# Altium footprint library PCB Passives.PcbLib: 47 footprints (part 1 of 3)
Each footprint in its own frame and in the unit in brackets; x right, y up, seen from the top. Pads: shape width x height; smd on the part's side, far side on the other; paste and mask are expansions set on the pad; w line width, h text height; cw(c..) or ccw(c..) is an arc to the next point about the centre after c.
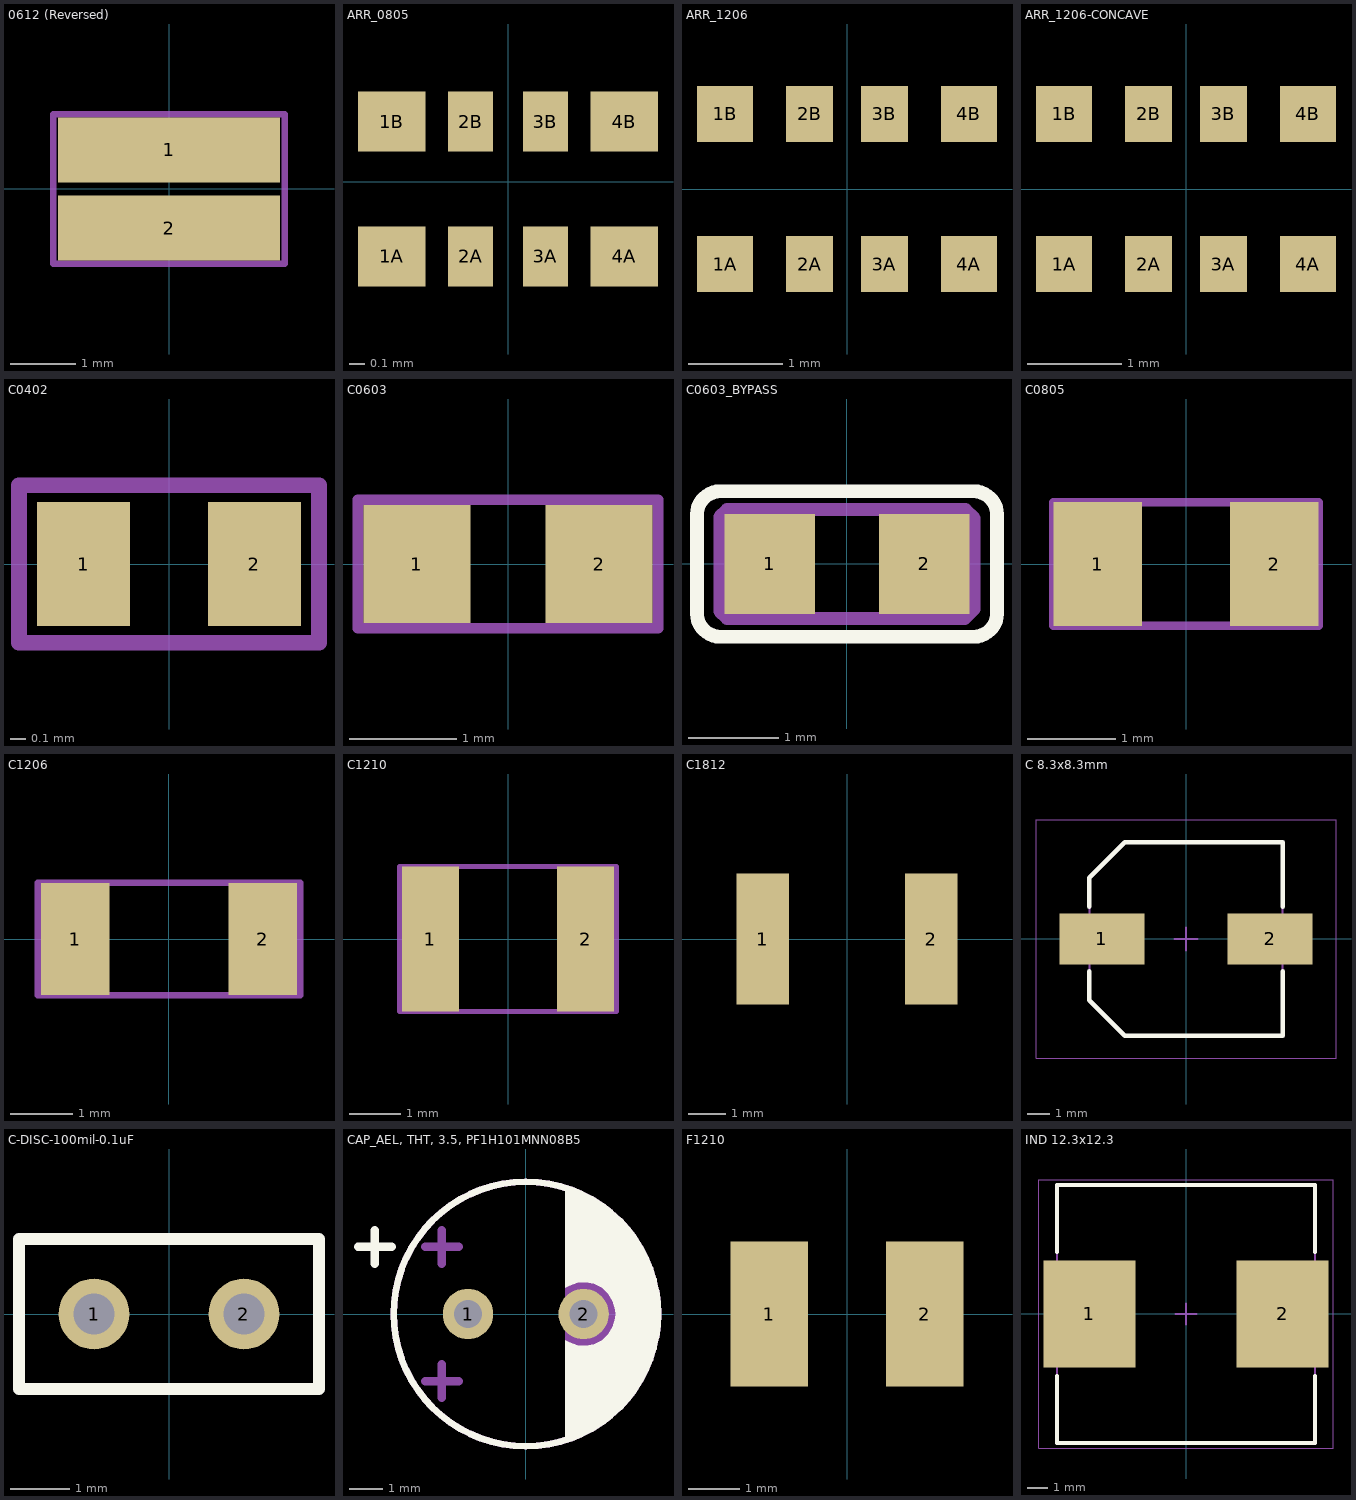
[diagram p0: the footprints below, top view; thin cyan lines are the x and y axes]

## 0612 (Reversed) [mm] "Chip Resistor, 2-Leads, Body 1,60x3,20mm, IPC Medium Density"
height 0.6
pads (2):
  rect 3.4x1 smd: 1(0,0.6) 2(0,-0.6)
Mechanical 29:
  lines w0.1: -1.778,-1.143 -1.778,1.143 1.778,1.143 1.778,-1.143 -1.778,-1.143
  text ".Designator" at -1.165,-0.3 h0.7
3D body "RESC1632X06N.step": height 0.6, standoff 0, extent -1.7,-0.9 1.7,0.9

## ARR_0805 [mm]
pads (8):
  rect 0.45x0.4 smd: 1A(-0.775,-0.5) 1B(-0.775,0.4) 4A(0.775,-0.5) 4B(0.775,0.4)
  rect 0.3x0.4 smd: 2A(-0.25,-0.5) 2B(-0.25,0.4) 3A(0.25,-0.5) 3B(0.25,0.4)
3D body "User Library-YC124.step": height 0.36, standoff 0, extent -1,-0.55 1,0.45

## ARR_1206 [mm]
height 0.6
pads (8):
  rect 0.6x0.6 smd: 1A(-1.3,-0.8) 1B(-1.3,0.8) 4A(1.3,-0.8) 4B(1.3,0.8)
  rect 0.5x0.6 smd: 2A(-0.4,-0.8) 2B(-0.4,0.8) 3A(0.4,-0.8) 3B(0.4,0.8)
3D body "User Library-YC164.step": height 0.55, standoff 0, extent -1.6,-0.8 1.6,0.8

## ARR_1206-CONCAVE [mm]
height 0.6
pads (8):
  rect 0.6x0.6 smd: 1A(-1.3,-0.8) 1B(-1.3,0.8) 4A(1.3,-0.8) 4B(1.3,0.8)
  rect 0.5x0.6 smd: 2A(-0.4,-0.8) 2B(-0.4,0.8) 3A(0.4,-0.8) 3B(0.4,0.8)
3D body "CAT16-x4.stp": height 0.6, standoff 0, extent -1.775,-0.825 1.575,0.925

## C0402 [mm] "0402 ceramic capacitor"
pads (2):
  rect 0.6x0.8 smd: 1(-0.55,0) 2(0.55,0)
Mechanical 29:
  lines w0.1: -0.965,-0.508 -0.965,0.508 0.965,0.508 0.965,-0.508 -0.965,-0.508
  text ".Designator" at -0.787,-0.279 h0.6
3D body "CAP_0402.step": height 0.5, standoff 0, extent -0.5,-0.25 0.5,0.25

## C0603 [mm] "0603 ceramic capacitor"
pads (2):
  rect 1x1.1 smd: 1(-0.85,0) 2(0.85,0)
Mechanical 29:
  lines w0.1: -1.4,-0.6 -1.4,0.6 1.4,0.6 1.4,-0.6 -1.4,-0.6
  text ".Designator" at -1.2,-0.2 h0.6
3D body "CAP_0603.step": height 0.8, standoff 0, extent -0.8,-0.4 0.8,0.4

## C0603_BYPASS [mm] "0603 ceramic capacitor"
pads (2):
  rect 1x1.1 smd: 1(-0.85,0) 2(0.85,0)
Top Overlay:
  lines w0.152: -1.651,-0.546 ccw(c-1.397,-0.546) -1.397,-0.8 1.397,-0.8 ccw(c1.397,-0.546) 1.651,-0.546 1.651,0.546 ccw(c1.397,0.546) 1.397,0.8 -1.397,0.8 ccw(c-1.397,0.546) -1.651,0.546 -1.651,-0.546
Mechanical 29:
  lines w0.14: -1.4,-0.521 -1.4,0.521 -1.321,0.6 1.305,0.6 1.4,0.505 1.4,-0.495 1.295,-0.6 -1.321,-0.6 -1.4,-0.521
  text ".Designator" at -0.635,-0.254 h0.51
3D body "CAP_0603.step": height 0.8, standoff 0, extent -0.8,-0.4 0.8,0.4

## C0805 [mm] "0805 ceramic capacitor"
pads (2):
  rect 1x1.4 smd: 1(-1,0) 2(1,0)
Mechanical 29:
  lines w0.1: -1.5,-0.7 1.5,-0.7 1.5,0.7 -1.5,0.7 -1.5,-0.7
  text ".Designator" at -1.3,-0.2 h0.6
3D body "CAP_0805.step": height 0.6, standoff 0, extent -1,-0.625 1,0.625

## C1206 [mm] "1206 ceramic capacitor"
pads (2):
  rect 1.1x1.8 smd: 1(-1.5,0) 2(1.5,0)
Mechanical 29:
  lines w0.1: -2.1,-0.9 -2.1,0.9 2.1,0.9 2.1,-0.9 -2.1,-0.9
  text ".Designator" at -1.8,-0.233 h0.7
3D body "CAP_1206.step": height 0.76, standoff -0.01, extent -1.6,-0.8 1.6,0.8

## C1210 [mm] "1210 capacitor"
pads (2):
  rect 1.1x2.8 smd: 1(-1.5,0) 2(1.5,0)
Mechanical 29:
  lines w0.1: -2.1,-1.4 2.1,-1.4 2.1,1.4 -2.1,1.4 -2.1,-1.4
  text ".Designator" at -1.8,-0.4 h0.8
3D body "User Library-SMD CAPACITOR.step": height 0.77, standoff -0.01, extent -1.6,-1.25 1.6,1.25

## C1812 [mm] "1812 capacitor"
pads (2):
  rect 1.4x3.5 smd: 1(-2.25,0) 2(2.25,0)
3D body "User Library-SMD CAPACITOR(1).step": height 1, standoff 0, extent -2.25,-1.6 2.25,1.6

## C 8.3x8.3mm [mm] "Aluminum Electrolytic Capacitor, Body 8.30x8.30x11.70mm, IPC Low Density"
height 11.7
pads (2):
  rect 3.75x2.25 smd: 1(-3.7,0) 2(3.7,0)
Top Overlay:
  lines w0.2: -4.25,-1.425 -4.25,-2.688 -2.688,-4.25 4.25,-4.25 4.25,-1.425 ; -4.25,1.425 -4.25,2.687 -2.688,4.25 4.25,4.25 4.25,1.425
Mechanical 13:
  lines w0.1: -4.25,-2.688 -2.688,-4.25 4.25,-4.25 4.25,4.25 -2.688,4.25 -4.25,2.687 -4.25,-2.688
Mechanical 15:
  lines w0.05: -6.6,-5.25 -6.6,5.25 6.6,5.25 6.6,-5.25 -6.6,-5.25
  lines w0.1: -0.5,0 0.5,0 ; 0,-0.5 0,0.5
3D body: height 3.9, standoff 0, extent -4.25,-4.25 4.25,4.25
3D body: height 11.7, standoff 0, extent -4.25,-4.25 4.25,4.247

## C-DISC-100mil-0.1uF [mm]
pads (2):
  round 1.2 hole 0.7: 1(-1.27,0) 2(1.27,0)
Top Overlay:
  lines w0.2: -2.54,-1.27 2.54,-1.27 2.54,1.27 -2.54,1.27 -2.54,-1.27
3D body "10pF Ceramic Disc 2.STEP": height 6.16, standoff -7.87, extent -2.35,-1.25 2.35,1.25

## CAP_AEL, THT, 3.5, PF1H101MNN08B5 [mm] "Capacitor: electrolytic; THT; 100uF; 50VDC; ¨8x11.5mm; Pitch:3.5mm"
pads (2):
  round 1.524 hole 0.85 paste-3: 1(-1.75,0) 2(1.75,0)
Top Overlay:
  circle w0.2: c0,0 r4
  region: 1.75,0
  region: 2.718,0 4,0 4,-0.318 3.9,-0.945 3.702,-1.548 3.411,-2.113 3.035,-2.625 2.583,-3.071 2.066,-3.44 1.497,-3.723 1.194,-3.818 1.194,-0.792 1.307,-0.86 1.555,-0.948 1.818,-0.965 2.075,-0.911 2.309,-0.79 2.501,-0.61 2.638,-0.385 2.709,-0.132
  region: 2.718,0 4,0 4,0.318 3.9,0.945 3.702,1.548 3.411,2.113 3.035,2.625 2.583,3.071 2.066,3.44 1.497,3.723 1.194,3.818 1.194,0.792 1.307,0.86 1.555,0.948 1.818,0.965 2.075,0.911 2.309,0.79 2.501,0.61 2.638,0.385 2.709,0.132
  lines w0.254: -5.08,2.032 -4.064,2.032 ; -4.572,1.524 -4.572,2.54
Mechanical 29:
  circle w0.2: c0,0 r4
  region: 1.194,3.817 1.497,3.723 2.066,3.44 2.583,3.071 3.035,2.625 3.411,2.113 3.702,1.548 3.9,0.945 4,0.317 4,-0.318 3.9,-0.945 3.702,-1.548 3.411,-2.113 3.035,-2.625 2.583,-3.071 2.066,-3.44 1.497,-3.723 1.194,-3.818
  region: 1.75,0
  lines w0.254: -3.048,-2.032 -2.032,-2.032 ; -3.048,2.032 -2.032,2.032 ; -2.54,-2.54 -2.54,-1.524 ; -2.54,1.524 -2.54,2.54
3D body "User Library-Cap electro 8x11_5x3_5mm.step": height 11.93, standoff -3.58, extent -4.025,-4.025 4.026,4.026

## F1210 [mm]
pads (2):
  rect 1.5x2.8 smd: 1(-1.5,0) 2(1.5,0)
3D body "User Library-Fuse1210.step": height 0.67, standoff 0, extent -1.607,-1.287 1.608,1.288

## IND 12.3x12.3 [mm] "Precision Wire Wound Inductor, 2-Leads, Body 12.30x12.30mm, IPC Medium Density"
height 6
pads (2):
  rect 4.4x5.1 smd: 1(-4.6,0) 2(4.6,0)
Top Overlay:
  lines w0.2: -6.15,-2.95 -6.15,-6.15 6.15,-6.15 6.15,-2.95 ; -6.15,2.95 -6.15,6.15 6.15,6.15 6.15,2.95
Mechanical 13:
  lines w0.1: -6.15,-6.15 6.15,-6.15 6.15,6.15 -6.15,6.15 -6.15,-6.15
Mechanical 15:
  lines w0.05: -7.025,-6.4 7.025,-6.4 7.025,6.4 -7.025,6.4 -7.025,-6.4
  lines w0.1: -0.5,0 0.5,0 ; 0,-0.5 0,0.5
3D body: height 6, standoff 0, extent -6.15,-6.15 6.15,6.15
